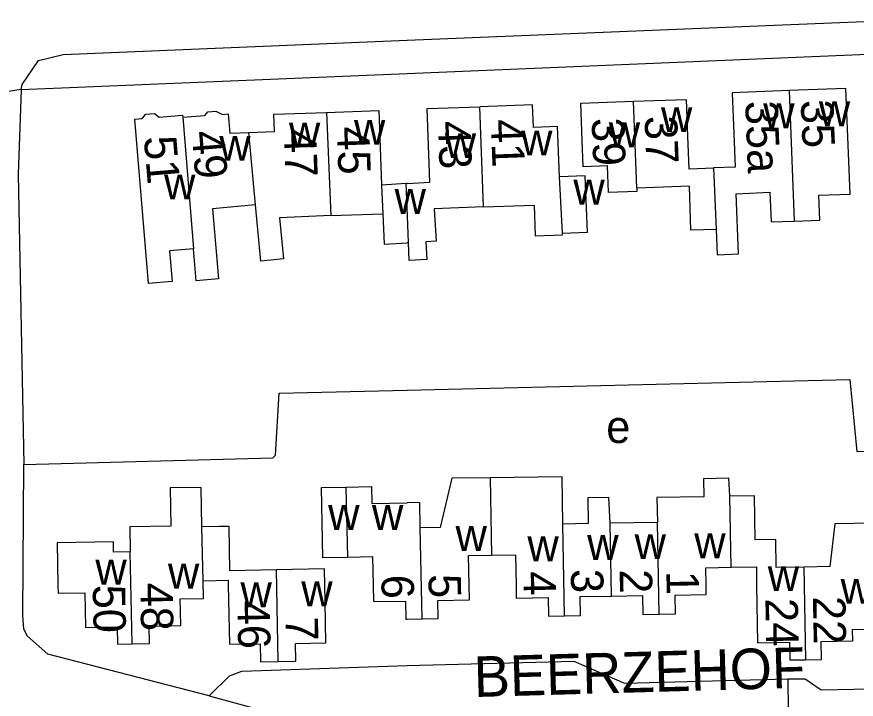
# Model space of a CAD drawing. Extents: x 156721 to 158827, y 386657 to 388950.
# Drawn here: x 158001.9 to 158105.4, y 387735.9 to 387820.1 of the extents above; entities that cross this region are included whole.
import ezdxf

# ---------------------------------------------------------------- set-up
doc = ezdxf.new("R2010")
doc.units = 0
for name, color, linetype in [('BLT_Basislijn', 7, 'Continuous'), ('BLT_Bebouwing', 7, 'Continuous'), ('BLT_Centroide', 7, 'Continuous'), ('BLT_Huisnummer', 7, 'Continuous'), ('BLT_Onderverdeling_panden', 7, 'Continuous'), ('BLT_Straatnaam', 7, 'Continuous'), ('BLT_Vlakafsluiter', 7, 'Continuous')]:
    doc.layers.add(name, color=color, linetype=linetype)

msp = doc.modelspace()

# ---------------------------------------------------------------- linework, layer by layer
at = {"layer": 'BLT_Basislijn'}
for p, q in [((158002.39, 387811.1), (158050, 387813.1)), ((158096.94, 387738.43), (158096.98, 387734.5)), ((158025.59, 387736.34), (158031.01, 387734.86))]:
    msp.add_line(p, q, dxfattribs=at)
for points in [[(158050, 387817.19), (158120.45, 387820.09), (158170.93, 387819.93), (158235.15, 387818.28)], [(158002.39, 387811.1), (158002.53, 387811.75), (158004.55, 387814.7), (158007.56, 387815.45), (158050, 387817.19)], [(158050, 387813.1), (158127.35, 387816.35), (158166.43, 387816.35), (158235.29, 387813.71)], [(158002.39, 387811.1), (158002.02, 387800.65), (158002.73, 387764.86)], [(158050, 387774.05), (158104.59, 387775.34), (158105.44, 387766.45), (158108.59, 387766.5), (158109.06, 387766.52)], [(158002.73, 387764.86), (158033.44, 387765.7), (158033.76, 387766.02), (158034.21, 387773.68), (158050, 387774.05)], [(158025.59, 387736.34), (158005.68, 387741.47), (158003.18, 387743.7), (158002.71, 387744.57), (158002.61, 387746.24), (158002.73, 387764.86)], [(158025.59, 387736.34), (158028.1, 387738.8), (158029.6, 387739.38), (158050, 387740.07)], [(158050, 387740.07), (158070.57, 387740.61), (158076.79, 387737.91), (158096.94, 387738.43)], [(158096.94, 387738.43), (158099.08, 387738.44), (158101.06, 387737.07), (158109.15, 387737.24), (158109.69, 387737.25)]]:
    msp.add_lwpolyline(points, dxfattribs=at)
at = {"layer": 'BLT_Bebouwing'}
for p, q in [((158049.88, 387799.52), (158046.84, 387799.34)), ((158040.6, 387795.56), (158047, 387795.79)), ((158080.87, 387757.73), (158075.02, 387757.63)), ((158050, 387745.79), (158051.83, 387745.82))]:
    msp.add_line(p, q, dxfattribs=at)
for points in [[(158097.73, 387794.89), (158100.88, 387795.02), (158100.76, 387798.07), (158104.62, 387798.23), (158104.45, 387802.22), (158104.29, 387806.26), (158104.09, 387811.26), (158097.09, 387810.98)], [(158097.09, 387810.98), (158090.08, 387810.69), (158090.28, 387805.7), (158090.45, 387801.55), (158087.76, 387801.44)], [(158068.78, 387800.34), (158068.56, 387806.54), (158065.56, 387806.43), (158065.46, 387809.22), (158058.96, 387808.99)], [(158078.31, 387798.96), (158078.32, 387798.55), (158074.84, 387798.42), (158074.72, 387801.69), (158071.69, 387801.58), (158071.57, 387804.88), (158071.41, 387809.43), (158077.91, 387809.66)], [(158077.91, 387809.66), (158084.41, 387809.9), (158084.57, 387805.37), (158084.72, 387801.35), (158084.77, 387801.35), (158087.76, 387801.44)], [(158023.64, 387791.48), (158020.68, 387791.23), (158021, 387787.45), (158018.11, 387787.21), (158016.41, 387807.47), (158017.32, 387807.54), (158017.76, 387808.07), (158018.86, 387808.17), (158019.42, 387807.69), (158022.31, 387807.94), (158022.33, 387807.69)], [(158022.33, 387807.69), (158025.05, 387807.91), (158025.42, 387808.35), (158026.41, 387808.43), (158027.24, 387808.04), (158027.92, 387808.1), (158028.12, 387805.72), (158030.47, 387805.8)], [(158030.47, 387805.8), (158033.64, 387805.92), (158033.56, 387808.07), (158040.07, 387808.3)], [(158040.07, 387808.3), (158046.51, 387808.53), (158046.67, 387803.97), (158046.84, 387799.34)], [(158050, 387799.52), (158052.78, 387799.68), (158052.46, 387808.76), (158058.96, 387808.99)], [(158069.14, 387793.4), (158072.22, 387793.51), (158071.97, 387800.46), (158068.78, 387800.34)], [(158050, 387799.52), (158049.88, 387799.52)], [(158088.1, 387793.86), (158084.98, 387793.77), (158084.83, 387799.2), (158078.31, 387798.96)], [(158088.1, 387793.86), (158088.24, 387790.74), (158090.88, 387790.86), (158090.58, 387798.27)], [(158090.58, 387798.27), (158094.73, 387798.44), (158094.88, 387794.78), (158097.73, 387794.89)], [(158031.3, 387796.89), (158026.01, 387796.4), (158026.73, 387787.75), (158023.97, 387787.52), (158023.64, 387791.48)], [(158040.6, 387795.56), (158034.27, 387795.31), (158034.74, 387790.22), (158031.94, 387789.96), (158031.3, 387796.89)], [(158059.4, 387796.63), (158053.35, 387796.42), (158053.57, 387792.42), (158052.31, 387792.35), (158052.44, 387790.14), (158050.26, 387790.01), (158050.17, 387792.23)], [(158059.4, 387796.63), (158065.65, 387796.86), (158065.79, 387793.06), (158069.15, 387793.18), (158069.14, 387793.4)], [(158047, 387795.79), (158047.16, 387792.05), (158050, 387792.22)], [(158050.17, 387792.23), (158050, 387792.22)], [(158060.25, 387763.23), (158055.49, 387763.17), (158054.05, 387757.09), (158051.62, 387757.06)], [(158069.21, 387757.52), (158069.12, 387763.33), (158060.25, 387763.23)], [(158089.79, 387760.95), (158089.68, 387763.17), (158086.54, 387763.11), (158086.57, 387760.89), (158080.81, 387760.79), (158080.87, 387757.73)], [(158024.68, 387757.17), (158024.59, 387762.03), (158020.77, 387761.97), (158020.86, 387757.25), (158015.8, 387757.16), (158015.86, 387754.09)], [(158042.66, 387753.4), (158039.61, 387753.35), (158039.45, 387762.04), (158042.45, 387762.09)], [(158042.45, 387762.09), (158045.59, 387762.15), (158045.63, 387760.07), (158050, 387760.15)], [(158075.02, 387757.63), (158074.89, 387760.79), (158072.29, 387760.74), (158072.34, 387757.58), (158069.21, 387757.52)], [(158098.96, 387752.22), (158095.51, 387752.17), (158095.45, 387755.61), (158092.93, 387755.56), (158092.83, 387761.01), (158089.79, 387760.95)], [(158051.62, 387757.06), (158051.57, 387760.17), (158050, 387760.15)], [(158107.63, 387744.54), (158107.41, 387757.62), (158102.74, 387757.54), (158102.11, 387752.28), (158098.96, 387752.22)], [(158033.88, 387751.88), (158028.14, 387751.77), (158028.04, 387757.23), (158026.82, 387757.21), (158024.68, 387757.17)], [(158015.86, 387754.09), (158013.79, 387754.05), (158013.77, 387755.33), (158006.83, 387755.2), (158006.93, 387750), (158006.94, 387748.99), (158010.25, 387749.05), (158010.33, 387744.78), (158014.25, 387744.85), (158014.29, 387742.71), (158016.09, 387742.74)], [(158045.88, 387747.95), (158045.84, 387750), (158045.78, 387753.46), (158042.66, 387753.4)], [(158051.83, 387745.82), (158053.83, 387745.86), (158053.79, 387748.09), (158057.68, 387748.16), (158057.64, 387750), (158057.58, 387753.64), (158060.38, 387753.69)], [(158060.38, 387753.69), (158063.36, 387753.74), (158063.43, 387750), (158063.46, 387748.39), (158067.4, 387748.46), (158067.44, 387746.17), (158069.42, 387746.2)], [(158081.08, 387746.41), (158083.08, 387746.44), (158083.04, 387748.75), (158086.89, 387748.82), (158086.86, 387750), (158086.83, 387752.13), (158089.95, 387752.19)], [(158089.95, 387752.19), (158093.07, 387752.25), (158093.1, 387750), (158093.22, 387742.89), (158097.15, 387742.95), (158097.19, 387740.76), (158099.15, 387740.79)], [(158039.9, 387747.87), (158039.86, 387750), (158039.82, 387751.98), (158033.88, 387751.88)], [(158016.09, 387742.74), (158018.23, 387742.78), (158018.19, 387744.93), (158022.08, 387745), (158022.02, 387748.28), (158024.88, 387748.33), (158024.83, 387750.52)], [(158024.83, 387750.52), (158027.92, 387750.58), (158027.93, 387750), (158028.07, 387742.7), (158031.86, 387742.76), (158031.9, 387740.54), (158034.08, 387740.58)], [(158045.88, 387747.95), (158049.78, 387748.02), (158049.82, 387745.79), (158050, 387745.79)], [(158069.42, 387746.2), (158071.39, 387746.24), (158071.35, 387748.57), (158075.19, 387748.64)], [(158075.19, 387748.64), (158079.03, 387748.71), (158079.07, 387746.37), (158081.08, 387746.41)], [(158034.08, 387740.58), (158036.26, 387740.62), (158036.22, 387742.8), (158039.99, 387742.87), (158039.9, 387747.87)], [(158099.15, 387740.79), (158101.11, 387740.82), (158101.07, 387743.04), (158104.95, 387743.1), (158104.92, 387744.5), (158107.63, 387744.54)]]:
    msp.add_lwpolyline(points, dxfattribs=at)
at = {"layer": 'BLT_Onderverdeling_panden'}
for p, q in [((158097.09, 387810.98), (158097.73, 387794.89)), ((158078.31, 387798.96), (158077.91, 387809.66)), ((158040.07, 387808.3), (158040.6, 387795.56)), ((158059.4, 387796.63), (158058.96, 387808.99)), ((158022.33, 387807.69), (158023.64, 387791.48)), ((158031.3, 387796.89), (158030.47, 387805.8)), ((158087.76, 387801.44), (158088.1, 387793.86)), ((158069.14, 387793.4), (158068.78, 387800.34)), ((158046.84, 387799.34), (158047, 387795.79)), ((158050, 387796.57), (158049.88, 387799.52)), ((158050.17, 387792.23), (158050, 387796.57)), ((158060.25, 387763.23), (158060.38, 387753.69)), ((158042.45, 387762.09), (158042.66, 387753.4)), ((158089.95, 387752.19), (158089.79, 387760.95)), ((158069.42, 387746.2), (158069.21, 387757.52)), ((158075.19, 387748.64), (158075.02, 387757.63)), ((158081.08, 387746.41), (158080.87, 387757.73)), ((158024.83, 387750.52), (158024.68, 387757.17)), ((158051.83, 387745.82), (158051.62, 387757.06)), ((158016.09, 387742.74), (158015.86, 387754.09)), ((158099.15, 387740.79), (158098.96, 387752.22)), ((158034.08, 387740.58), (158033.88, 387751.88))]:
    msp.add_line(p, q, dxfattribs=at)
at = {"layer": 'BLT_Vlakafsluiter'}
msp.add_line((158002.39, 387811.1), (157994.3, 387809.87), dxfattribs=at)

# ---------------------------------------------------------------- texts
at = {"layer": 'BLT_Centroide'}
for s, p in [('w', (158093.91, 387806.34)), ('w', (158100.77, 387806.59)), ('w', (158081.3, 387805.86)), ('w', (158035.42, 387803.97)), ('w', (158043.44, 387804.3)), ('w', (158074.86, 387803.98)), ('w', (158064.05, 387802.98)), ('w', (158026.83, 387802.33)), ('w', (158054.64, 387802.66)), ('w', (158020.02, 387797.56)), ('w', (158070.5, 387796.92)), ('w', (158048.45, 387795.78)), ('e', (158074.55, 387767.52)), ('w', (158040.26, 387756.78)), ('w', (158045.66, 387756.78)), ('w', (158055.97, 387754.19)), ('w', (158078.05, 387753.19)), ('w', (158085.41, 387753.3)), ('w', (158064.83, 387752.92)), ('w', (158072.2, 387753.08)), ('w', (158011.55, 387750.05)), ('w', (158020.5, 387749.56)), ('w', (158094.47, 387749.25)), ('w', (158029.45, 387747.25)), ('w', (158036.94, 387747.38)), ('w', (158103.45, 387747.69))]:
    msp.add_text(s, height=4, dxfattribs=at).set_placement(p)
at = {"layer": 'BLT_Huisnummer'}
for s, rotation, p in [('35a', 272.3044, (158091.68, 387809.67)), ('35', 272.426, (158098.53, 387809.78)), ('43', 272.0423, (158053.79, 387807.18)), ('41', 272.0462, (158060.31, 387807.41)), ('39', 272.0778, (158072.75, 387807.56)), ('37', 272.079, (158079.28, 387807.82)), ('47', 272.0749, (158034.77, 387806.2)), ('45', 272.0749, (158041.32, 387806.51)), ('51', 274.7931, (158017.52, 387805.25)), ('49', 274.6203, (158023.42, 387805.9)), ('5', 271.0421, (158052.62, 387751.33)), ('4', 271.0421, (158064.33, 387751.66)), ('3', 271.0421, (158070.18, 387751.95)), ('2', 271.0421, (158076.2, 387751.9)), ('1', 271.0421, (158081.96, 387751.71)), ('48', 271.0431, (158017.08, 387750.26)), ('6', 271.0421, (158046.81, 387751.24)), ('50', 271.0431, (158011.22, 387750.01)), ('24', 271.1319, (158094.17, 387748.35)), ('22', 271.1319, (158100.03, 387748.6)), ('46', 271.0431, (158029.05, 387748.04)), ('7', 271.0421, (158035, 387746.05))]:
    msp.add_text(s, height=4, rotation=rotation, dxfattribs=at).set_placement(p)
at = {"layer": 'BLT_Straatnaam'}
msp.add_text('BEERZEHOF', height=5, rotation=1.6397, dxfattribs=at).set_placement((158058.28, 387736.18))

doc.saveas('drawing.dxf')
